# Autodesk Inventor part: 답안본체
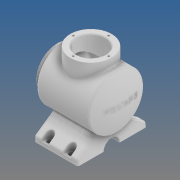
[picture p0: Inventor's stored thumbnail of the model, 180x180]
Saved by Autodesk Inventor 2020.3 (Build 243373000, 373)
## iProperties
Created: 2021-04
Part Number: 답안본체
Material: 알루미늄 6061
Document SubType Name: Modeling
Designer: EZDESIGN
Density: 2.7 g/cm^3
Appearance: 기본값
Mass: 1685.26 g
Surface Area: 1049.95 cm^2
Volume: 624.172 cm^3
Author: EZDESIGN
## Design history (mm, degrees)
sketch "스케치1"
  geometry: L1 (15, 50)-(106.454, 50); L2 (0, 0)-(120, 0); L3 (0, 27)-(22, 27); L4 (22, 27)-(22, 37); L5 (25, 40)-(99.903, 40); L6 (12, 47)-(12, 41); L7 (9, 38)-(0, 38); L8 (0, 38)-(0, 27); A1 r 113 centre (7, 0) between (120, 0) and (109.166, 48.282); A2 r 103 centre (7, 0) between (110, 0) and (102.69, 38.11); A3 r 3 centre (15, 47) between (15, 50) and (12, 47); A4 r 3 centre (9, 41) between (9, 38) and (12, 41); A5 r 3 centre (25, 37) between (25, 40) and (22, 37); A6 r 3 centre (99.903, 37) between (102.69, 38.11) and (99.903, 40); A7 r 3 centre (106.454, 47) between (109.166, 48.282) and (106.454, 50); 5 further points
  constraints: 16 end point, 16 point on circle, 10 point on line, 10 tangent, 7 centre point, 5 perpendicular, 2 equal radius, 1 horizontal, 1 other
  dimensions: "d0" = 120 distance of L2.start L2.end; "d13" = 226 diameter of A1; "d15" = 108 horizontal distance of L2.end point (12, 50); "d16" = 10 radial gap between concentric circles of A1 A2; "d17" = 22 distance of L3.start L3.end; "d18" = 54 diameter of L3 L2; "d19" = 100 diameter of L1 L2; "d20" = 12 distance of point (12, 38) L7.end; "d21" = 76 diameter of L7 L2; "d139" = 3 radius of A3; "d140" = 3 radius of A5 (derived); "d141" = 3 radius of A7 (derived)
revolve "회전2" sketch "스케치1" stored, may be unused: angle "d23" = 90 deg
node "작업 평면1"
sketch "스케치2"
  geometry: L1 (9.266, -30.075)-(62, -67); L2 (62, -67)-(62, -77); L3 (62, -77)-(15, -77); L4 (-9.266, -30.075)-(-62, -67); L5 (-62, -67)-(-62, -77); L6 (-62, -77)-(-15, -77); L7 (0, 0)-(0, -27); L8 (9.266, -30.075)-(-9.266, -30.075); C1 r 50 at (0, 0) reference; A1 r 15 centre (0, -77) between (15, -77) and (-15, -77); 4 further points
  constraints: 16 end point, 2 perpendicular, 2 point on circle, 2 point on line, 2 vertical, 2 vertical alignment, 1 centre point, 1 horizontal, 1 other
  dimensions: "d25" = 30 diameter of A1; "d26" = 124 distance between parallel lines of L5 L2; "d27" = 10 distance of L4.end L5.end; "d28" = 10 distance of L1.end L2.end; "d29" = 62 horizontal distance of L5.end point (0, 0); "d30" = 55 deg angle of L2 L1; "d31" = 55 deg angle of L5 L4; "d32" = 77 distance from line of L6 point (0, 0); "d33" = 15 distance edge to line of A1 L6; "d41" = 35.30635 distance from line of point (26.694, -42.278) L2; "d42" = 0 distance from line of point (26.694, -42.278) L1; "d43" = 88.69365 distance from line of point (-26.694, -42.278) L2; "d45" = 46.92509 distance between parallel lines of L8 L3; "d46" = 30.6217 distance from line of point (-26.694, -42.278) L1
extrude "돌출2" join sketch "스케치2" distance "d47" = 80; taper "d48" = 0 deg
node "작업 평면2"
sketch "스케치8"
  geometry: C1 r 38 at (42, -15); 1 further point
  constraints: 1 centre point, 1 horizontal alignment
  dimensions: "d79" = 76 diameter of C1; "d80" = 62 distance of point (-20, -15) C1.centre
extrude "돌출4" join sketch "스케치8" stored distance "d81" = 142; taper "d82" = 0 deg
sketch "스케치9"
  geometry: C1 r 38 at (0, 0) reference; C2 r 27 at (0, 0); 1 further point
  constraints: 1 centre point, 1 coincident
  dimensions: "d83" = 54 diameter of C2
extrude "돌출5" cut sketch "스케치9" distance "d84" = 50; taper "d85" = 0 deg
sketch "스케치10"
  geometry: C1 r 27 at (0, 0) reference; C2 r 38 at (0, 0) reference; A1 r 32.5 centre (0, 0) between (0, 32.5) and (-32.5, 0); 3 further points
  constraints: 4 point on circle, 2 horizontal alignment, 2 vertical alignment, 1 centre point, 1 coincident
  dimensions: "d86" = 65 diameter of A1
hole "구멍2" sketch "스케치10" at (0, 32.5), (-32.5, 0), (0, -32.5), (32.5, 0) diameter "d87" = 3.242; stored, may be unused: countersink angle "d91" = 90 deg, drill point angle "d93" = 118 deg; dims "d88" = 8, "d89" = 4, "d90" = 2, "d92" = 10
sketch "스케치11"
  geometry: C1 r 27 at (0, 0) reference; C2 r 38 at (0, 0) reference; A1 r 32.5 centre (0, 0) between (0, 32.5) and (-32.5, 0); 3 further points
  constraints: 4 point on circle, 2 horizontal alignment, 2 vertical alignment, 1 centre point, 1 coincident
  dimensions: "d94" = 65 diameter of A1
hole "구멍3" sketch "스케치11" at (0, 32.5), (-32.5, 0), (0, -32.5), (32.5, 0) diameter "d95" = 3.242; stored, may be unused: countersink angle "d99" = 90 deg, drill point angle "d101" = 118 deg; dims "d96" = 8, "d97" = 4, "d98" = 2, "d100" = 10
node "작업 평면4"
sketch "스케치14"
  geometry: L1 (0, 47)-(80, 47) reference; L2 (80, 47)-(80, 0) reference; L3 (13, 39)-(13, 47); L4 (27, 39)-(27, 47); L5 (53, 39)-(53, 47); L6 (67, 39)-(67, 47); L7 (0, -77)-(80, -77) reference; L8 (80, -30)-(80, -77) reference; L9 (13, -69)-(13, -77); L10 (27, -69)-(27, -77); L11 (53, -69)-(53, -77); L12 (67, -69)-(67, -77); A1 r 7 centre (20, 39) between (13, 39) and (27, 39); A2 r 7 centre (60, 39) between (53, 39) and (67, 39); A3 r 7 centre (20, -69) between (13, -69) and (27, -69); A4 r 7 centre (60, -69) between (53, -69) and (67, -69); 1 further point
  constraints: 16 end point, 8 perpendicular, 8 point on circle, 8 point on line, 8 tangent, 4 centre point, 1 horizontal alignment
  dimensions: "d112" = 14 diameter of A2; "d113" = 14 diameter of A1; "d114" = 8 distance from line of L1 A1.centre; "d115" = 8 distance from line of L1 A2.centre; "d116" = 20 distance from line of L2 A2.centre; "d117" = 40 distance of A2.centre A1.centre; "d120" = 14 diameter of A3; "d121" = 14 diameter of A4; "d122" = 8 distance from line of L7 A3.centre; "d123" = 20 distance from line of L8 A4.centre; "d124" = 40 distance of A3.centre A4.centre
extrude "돌출6" cut sketch "스케치14" distance "d118" = 40 (= d124); taper "d119" = 0 deg
sketch "스케치15"
  geometry: L1 (0, 1.252)-(80, 1.252) reference; L2 (80, 1.252)-(80, -47) reference; L3 (80, -47)-(67, -47) reference; L4 (67, -47)-(67, -39) reference; L5 (53, -39)-(53, -47) reference; L6 (53, -47)-(27, -47) reference; L7 (27, -47)-(13, -47) reference; L8 (13, -47)-(0, -47) reference; L9 (0, -47)-(0, 1.252) reference; L10 (67, -47)-(53, -47) reference; L11 (27, -47)-(27, -39) reference; L12 (13, -39)-(13, -47) reference; L13 (80, 28.748)-(0, 28.748) reference; L14 (0, 28.748)-(0, 77) reference; L15 (0, 77)-(13, 77) reference; L16 (13, 77)-(13, 69) reference; L17 (27, 69)-(27, 77) reference; L18 (27, 77)-(53, 77) reference; L19 (53, 77)-(67, 77) reference; L20 (67, 77)-(80, 77) reference; L21 (80, 77)-(80, 28.748) reference; L22 (13, 77)-(27, 77) reference; L23 (53, 77)-(53, 69) reference; L24 (67, 69)-(67, 77) reference; C1 r 4.5 at (20, -39); C2 r 4.5 at (60, -39); C3 r 4.5 at (60, 69); C4 r 4.5 at (20, 69); A1 r 7 centre (60, -39) between (67, -39) and (53, -39) reference; A2 r 7 centre (20, -39) between (27, -39) and (13, -39) reference; A3 r 7 centre (20, 69) between (13, 69) and (27, 69) reference; A4 r 7 centre (60, 69) between (53, 69) and (67, 69) reference; 1 further point
  constraints: 4 centre point, 4 coincident
  dimensions: "d125" = 9 diameter of C1; "d126" = 9 diameter of C2; "d127" = 9 diameter of C3; "d128" = 9 diameter of C4
extrude "돌출7" cut sketch "스케치15" distance "d129" = 10; taper "d130" = 0 deg
fillet "모깎기1" dims "d132" = 3
chamfer "모따기1" distance "d133" = 1; stored, may be unused: second distance "d134" = 2, angle "d135" = 45 deg
chamfer "모따기2" distance "d136" = 1; stored, may be unused: second distance "d137" = 2, angle "d138" = 45 deg
fillet "모깎기2" dims "d142" = 3
fillet "모깎기3" dims "d143" = 3
node "작업 평면8"
sketch "스케치20"
  geometry: 2 further points
  constraints: 1 coincident, 1 other
feature "엠보싱1" sketch "스케치20" dims "d15" = 108, "d25" = 30, "d26" = 124, "d27" = 10, "d28" = 10, "d29" = 62, "d30" = 55 deg, "d31" = 55 deg, "d32" = 77, "d33" = 15, "d41" = 35.30635, "d42" = 0, "d43" = 88.69365, "d45" = 46.92509, "d46" = 30.6217, "d146" = 0.5, "d147" = 0
node "솔리드2"
node "절단 모서리 투영1"
node "절단 모서리 투영7"
node "절단 모서리 투영8"
node "절단 모서리 투영9"
node "절단 모서리 투영12"
feature "A9D066F2-1C7D-4E18-AEED-F7BC21143FA4" dims "d87" = 3.242, "d88" = 8, "d89" = 4, "d90" = 2, "d91" = 90 deg, "d92" = 10, "d93" = 118 deg
other parameters: "d78" = -142, "d107" = -6, "d145" = -174.25
